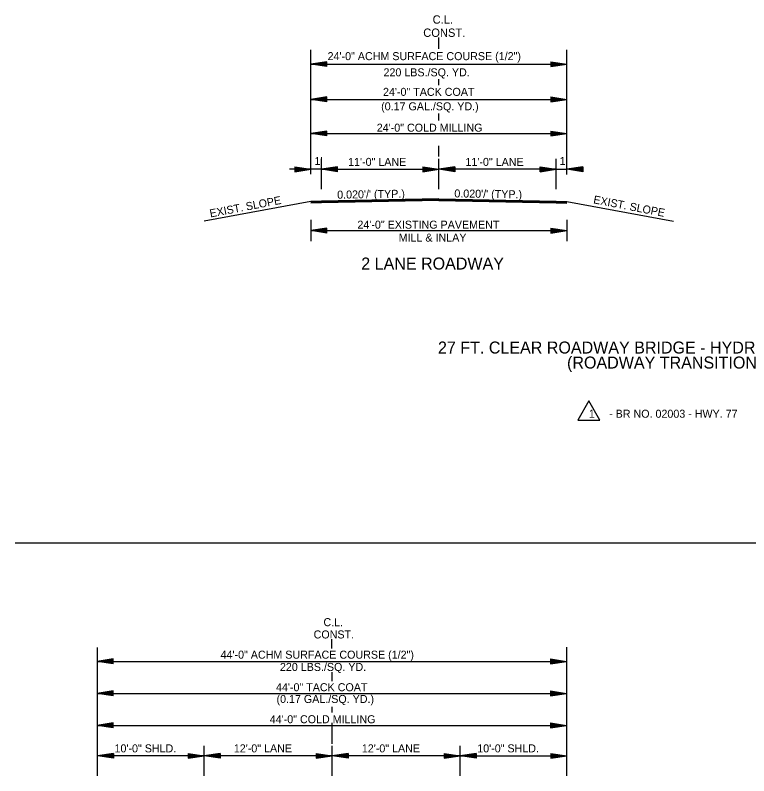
# Model space of a CAD drawing. Extents: x 549600 to 1930787, y -1955432 to 596640.
# Drawn here: x 551005 to 551693, y -1945136 to -1944424 of the extents above; entities that cross this region are included whole.
import ezdxf

# ---------------------------------------------------------------- set-up
doc = ezdxf.new("R2010")
doc.units = 0
doc.layers.add('R_Border', color=7, linetype='Continuous')
doc.layers.add('S_AREA_CALC', color=7, linetype='Continuous')

# ---------------------------------------------------------------- blocks, each defined once
blk = doc.blocks.new('ARROW')
at = {"layer": 'S_AREA_CALC'}
for p, q in [((-2, 0.3), (0, 0)), ((-2, 0.3), (-2, -0.3)), ((-2, 0.25), (-0.334, 0)), ((-2, 0.199), (-0.678, 0)), ((-2, 0.149), (-1.011, 0)), ((-2, 0.097), (-1.35, 0)), ((-2, 0.047), (-1.684, 0)), ((-2, -0.3), (0, 0)), ((-2, -0.098), (-1.35, 0)), ((-2, -0.199), (-0.678, 0)), ((-2, -0.25), (-0.334, 0)), ((-2, -0.149), (-1.011, 0)), ((-2, -0.047), (-1.684, 0))]:
    blk.add_line(p, q, dxfattribs=at)

msp = doc.modelspace()

# ---------------------------------------------------------------- linework, layer by layer
at = {"layer": 'R_Border'}
for p, q in [((551292.02, -1944597.88), (551282.02, -1944598.28)), ((551292.02, -1944598.18), (551282.02, -1944598.58)), ((551292.02, -1944598.48), (551282.02, -1944598.88)), ((551292.02, -1944598.78), (551282.02, -1944599.18)), ((551512.02, -1944597.88), (551522.02, -1944598.28)), ((551512.02, -1944598.18), (551522.02, -1944598.58)), ((551512.02, -1944598.48), (551522.02, -1944598.88)), ((551512.02, -1944598.78), (551522.02, -1944599.18)), ((551292.02, -1944599.08), (551282.02, -1944599.48)), ((551292.02, -1944599.38), (551282.02, -1944599.78)), ((551292.02, -1944599.55), (551282.02, -1944599.95)), ((551512.02, -1944599.08), (551522.02, -1944599.48)), ((551512.02, -1944599.38), (551522.02, -1944599.78)), ((551512.02, -1944599.55), (551522.02, -1944599.95)), ((551532.29, -1944803.08), (551552.96, -1944803.08)), ((551004.91, -1944917.94), (552066.18, -1944917.94)), ((551301.38, -1945008.4), (551301.38, -1945016.96)), ((551081.71, -1945029.1), (551521.71, -1945029.1)), ((551301.6, -1945039.33), (551301.6, -1945047.55)), ((551081.71, -1945059.1), (551521.71, -1945059.1)), ((551301.67, -1945071.61), (551301.67, -1945077.11)), ((551081.71, -1945089.1), (551521.71, -1945089.1))]:
    msp.add_line(p, q, dxfattribs=at)
msp.add_lwpolyline([(551552.96, -1944803.08), (551542.63, -1944785.18), (551532.29, -1944803.08)], dxfattribs=at)
at = {"layer": 'S_AREA_CALC'}
for p, q in [((551402.02, -1944455.12), (551402.02, -1944444.74)), ((551282.02, -1944572.61), (551282.02, -1944456.23)), ((551522.02, -1944573.09), (551522.02, -1944456.23)), ((551297.02, -1944467.35), (551282.02, -1944469.6)), ((551282.02, -1944469.6), (551522.02, -1944469.6)), ((551297.02, -1944471.85), (551282.02, -1944469.6)), ((551297.02, -1944467.73), (551284.52, -1944469.6)), ((551297.02, -1944471.48), (551284.52, -1944469.6)), ((551297.02, -1944468.11), (551287.1, -1944469.6)), ((551297.02, -1944471.09), (551287.1, -1944469.6)), ((551297.02, -1944468.48), (551289.6, -1944469.6)), ((551297.02, -1944470.72), (551289.6, -1944469.6)), ((551297.02, -1944468.87), (551292.14, -1944469.6)), ((551297.02, -1944470.33), (551292.14, -1944469.6)), ((551297.02, -1944469.25), (551294.65, -1944469.6)), ((551297.02, -1944469.95), (551294.65, -1944469.6)), ((551297.02, -1944471.85), (551297.02, -1944467.35)), ((551507.02, -1944467.35), (551522.02, -1944469.6)), ((551507.02, -1944467.35), (551507.02, -1944471.85)), ((551507.02, -1944467.73), (551519.51, -1944469.6)), ((551507.02, -1944468.11), (551516.93, -1944469.6)), ((551507.02, -1944468.48), (551514.44, -1944469.6)), ((551507.02, -1944468.87), (551511.89, -1944469.6)), ((551507.02, -1944469.25), (551509.39, -1944469.6)), ((551507.02, -1944471.85), (551522.02, -1944469.6)), ((551507.02, -1944470.34), (551511.89, -1944469.6)), ((551507.02, -1944471.09), (551516.93, -1944469.6)), ((551507.02, -1944471.48), (551519.51, -1944469.6)), ((551507.02, -1944470.72), (551514.44, -1944469.6)), ((551507.02, -1944469.95), (551509.39, -1944469.6)), ((551402.02, -1944489.34), (551402.02, -1944483.81)), ((551297.02, -1944500.32), (551282.02, -1944502.57)), ((551282.02, -1944502.57), (551522.02, -1944502.57)), ((551297.02, -1944504.82), (551282.02, -1944502.57)), ((551297.02, -1944500.69), (551284.52, -1944502.57)), ((551297.02, -1944504.44), (551284.52, -1944502.57)), ((551297.02, -1944501.07), (551287.1, -1944502.57)), ((551297.02, -1944504.06), (551287.1, -1944502.57)), ((551297.02, -1944501.45), (551289.6, -1944502.57)), ((551297.02, -1944503.68), (551289.6, -1944502.57)), ((551297.02, -1944501.83), (551292.14, -1944502.57)), ((551297.02, -1944503.29), (551292.14, -1944502.57)), ((551297.02, -1944502.21), (551294.65, -1944502.57)), ((551297.02, -1944502.92), (551294.65, -1944502.57)), ((551297.02, -1944504.82), (551297.02, -1944500.32)), ((551507.02, -1944500.32), (551522.02, -1944502.57)), ((551507.02, -1944500.32), (551507.02, -1944504.82)), ((551507.02, -1944500.69), (551519.51, -1944502.57)), ((551507.02, -1944501.07), (551516.93, -1944502.57)), ((551507.02, -1944501.45), (551514.44, -1944502.57)), ((551507.02, -1944501.84), (551511.89, -1944502.57)), ((551507.02, -1944502.21), (551509.39, -1944502.57)), ((551507.02, -1944504.82), (551522.02, -1944502.57)), ((551507.02, -1944503.3), (551511.89, -1944502.57)), ((551507.02, -1944504.06), (551516.93, -1944502.57)), ((551507.02, -1944504.44), (551519.51, -1944502.57)), ((551507.02, -1944503.68), (551514.44, -1944502.57)), ((551507.02, -1944502.92), (551509.39, -1944502.57)), ((551402.02, -1944522.31), (551402.02, -1944515.89)), ((551297.02, -1944532.29), (551282.02, -1944534.54)), ((551282.02, -1944534.54), (551522.02, -1944534.54)), ((551297.02, -1944536.79), (551282.02, -1944534.54)), ((551297.02, -1944532.67), (551284.52, -1944534.54)), ((551297.02, -1944536.42), (551284.52, -1944534.54)), ((551297.02, -1944533.05), (551287.1, -1944534.54)), ((551297.02, -1944536.03), (551287.1, -1944534.54)), ((551297.02, -1944533.42), (551289.6, -1944534.54)), ((551297.02, -1944535.66), (551289.6, -1944534.54)), ((551297.02, -1944533.81), (551292.14, -1944534.54)), ((551297.02, -1944535.27), (551292.14, -1944534.54)), ((551297.02, -1944534.19), (551294.65, -1944534.54)), ((551297.02, -1944534.89), (551294.65, -1944534.54)), ((551297.02, -1944536.79), (551297.02, -1944532.29)), ((551507.02, -1944532.29), (551522.02, -1944534.54)), ((551507.02, -1944532.29), (551507.02, -1944536.79)), ((551507.02, -1944532.67), (551519.51, -1944534.54)), ((551507.02, -1944533.05), (551516.93, -1944534.54)), ((551507.02, -1944533.42), (551514.44, -1944534.54)), ((551507.02, -1944533.81), (551511.89, -1944534.54)), ((551507.02, -1944534.19), (551509.39, -1944534.54)), ((551507.02, -1944536.79), (551522.02, -1944534.54)), ((551507.02, -1944535.28), (551511.89, -1944534.54)), ((551507.02, -1944536.03), (551516.93, -1944534.54)), ((551507.02, -1944536.42), (551519.51, -1944534.54)), ((551507.02, -1944535.66), (551514.44, -1944534.54)), ((551507.02, -1944534.89), (551509.39, -1944534.54)), ((551402.02, -1944556.06), (551402.02, -1944546.19)), ((551292.02, -1944586.74), (551292.02, -1944558.19)), ((551402.02, -1944586.74), (551402.02, -1944558.19)), ((551512.02, -1944586.74), (551512.02, -1944558.19)), ((551292.02, -1944568.08), (551262.02, -1944568.08)), ((551267.02, -1944565.83), (551282.02, -1944568.08)), ((551267.02, -1944565.83), (551267.02, -1944570.33)), ((551267.02, -1944566.2), (551279.51, -1944568.08)), ((551267.02, -1944566.59), (551276.93, -1944568.08)), ((551267.02, -1944566.96), (551274.44, -1944568.08)), ((551267.02, -1944567.35), (551271.89, -1944568.08)), ((551267.02, -1944567.73), (551269.39, -1944568.08)), ((551267.02, -1944570.33), (551282.02, -1944568.08)), ((551267.02, -1944568.81), (551271.89, -1944568.08)), ((551267.02, -1944569.57), (551276.93, -1944568.08)), ((551267.02, -1944569.95), (551279.51, -1944568.08)), ((551267.02, -1944569.2), (551274.44, -1944568.08)), ((551267.02, -1944568.43), (551269.39, -1944568.08)), ((551307.02, -1944565.83), (551292.02, -1944568.08)), ((551307.02, -1944570.33), (551292.02, -1944568.08)), ((551292.02, -1944568.08), (551402.02, -1944568.08)), ((551307.02, -1944566.2), (551294.52, -1944568.08)), ((551307.02, -1944569.95), (551294.52, -1944568.08)), ((551307.02, -1944566.59), (551297.1, -1944568.08)), ((551307.02, -1944569.57), (551297.1, -1944568.08)), ((551307.02, -1944566.96), (551299.6, -1944568.08)), ((551307.02, -1944569.2), (551299.6, -1944568.08)), ((551307.02, -1944567.34), (551302.14, -1944568.08)), ((551307.02, -1944568.81), (551302.14, -1944568.08)), ((551307.02, -1944567.73), (551304.65, -1944568.08)), ((551307.02, -1944568.43), (551304.65, -1944568.08)), ((551307.02, -1944570.33), (551307.02, -1944565.83)), ((551387.02, -1944565.83), (551402.02, -1944568.08)), ((551387.02, -1944565.83), (551387.02, -1944570.33)), ((551387.02, -1944566.2), (551399.51, -1944568.08)), ((551387.02, -1944566.59), (551396.93, -1944568.08)), ((551387.02, -1944566.96), (551394.44, -1944568.08)), ((551387.02, -1944567.35), (551391.89, -1944568.08)), ((551387.02, -1944567.73), (551389.39, -1944568.08)), ((551387.02, -1944570.33), (551402.02, -1944568.08)), ((551387.02, -1944568.81), (551391.89, -1944568.08)), ((551387.02, -1944569.57), (551396.93, -1944568.08)), ((551387.02, -1944569.95), (551399.51, -1944568.08)), ((551387.02, -1944569.2), (551394.44, -1944568.08)), ((551387.02, -1944568.43), (551389.39, -1944568.08)), ((551417.02, -1944565.83), (551402.02, -1944568.08)), ((551512.02, -1944568.08), (551402.02, -1944568.08)), ((551417.02, -1944570.33), (551402.02, -1944568.08)), ((551417.02, -1944566.2), (551404.52, -1944568.08)), ((551417.02, -1944569.95), (551404.52, -1944568.08)), ((551417.02, -1944566.59), (551407.1, -1944568.08)), ((551417.02, -1944569.57), (551407.1, -1944568.08)), ((551417.02, -1944566.96), (551409.6, -1944568.08)), ((551417.02, -1944569.2), (551409.6, -1944568.08)), ((551417.02, -1944567.35), (551412.14, -1944568.08)), ((551417.02, -1944568.81), (551412.14, -1944568.08)), ((551417.02, -1944567.73), (551414.65, -1944568.08)), ((551417.02, -1944568.43), (551414.65, -1944568.08)), ((551417.02, -1944565.83), (551417.02, -1944570.33)), ((551497.02, -1944565.83), (551512.02, -1944568.08)), ((551497.02, -1944570.33), (551497.02, -1944565.83)), ((551497.02, -1944566.2), (551509.51, -1944568.08)), ((551497.02, -1944566.59), (551506.93, -1944568.08)), ((551497.02, -1944566.96), (551504.44, -1944568.08)), ((551497.02, -1944567.34), (551501.89, -1944568.08)), ((551497.02, -1944567.73), (551499.39, -1944568.08)), ((551497.02, -1944570.33), (551512.02, -1944568.08)), ((551497.02, -1944568.81), (551501.89, -1944568.08)), ((551497.02, -1944569.57), (551506.93, -1944568.08)), ((551497.02, -1944569.95), (551509.51, -1944568.08)), ((551497.02, -1944569.2), (551504.44, -1944568.08)), ((551497.02, -1944568.43), (551499.39, -1944568.08)), ((551512.02, -1944568.08), (551522.02, -1944568.08)), ((551537.02, -1944565.83), (551522.02, -1944568.08)), ((551537.02, -1944570.33), (551522.02, -1944568.08)), ((551537.02, -1944566.2), (551524.52, -1944568.08)), ((551537.02, -1944569.95), (551524.52, -1944568.08)), ((551537.02, -1944566.59), (551527.1, -1944568.08)), ((551537.02, -1944569.57), (551527.1, -1944568.08)), ((551537.02, -1944566.96), (551529.6, -1944568.08)), ((551537.02, -1944569.2), (551529.6, -1944568.08)), ((551537.02, -1944567.35), (551532.14, -1944568.08)), ((551537.02, -1944568.81), (551532.14, -1944568.08)), ((551537.02, -1944567.73), (551534.65, -1944568.08)), ((551537.02, -1944568.43), (551534.65, -1944568.08)), ((551537.02, -1944565.83), (551537.02, -1944570.33)), ((551282.02, -1944598.28), (551181.95, -1944616.66)), ((551402.02, -1944595.68), (551292.02, -1944597.88)), ((551402.05, -1944595.98), (551292.02, -1944598.18)), ((551402.04, -1944596.28), (551292.02, -1944598.48)), ((551402.04, -1944596.58), (551292.02, -1944598.78)), ((551402.04, -1944596.88), (551292.02, -1944599.08)), ((551402.05, -1944597.18), (551292.02, -1944599.38)), ((551402.05, -1944597.35), (551292.02, -1944599.55)), ((551401.98, -1944597.35), (551512.02, -1944599.55)), ((551401.99, -1944596.88), (551512.02, -1944599.08)), ((551401.99, -1944597.18), (551512.02, -1944599.38)), ((551402, -1944596.58), (551512.02, -1944598.78)), ((551402.01, -1944595.98), (551512.02, -1944598.18)), ((551402.01, -1944596.28), (551512.02, -1944598.48)), ((551402.02, -1944595.68), (551512.02, -1944597.88)), ((551522.02, -1944598.28), (551622.09, -1944616.66)), ((551282.02, -1944615.54), (551282.02, -1944635.54)), ((551522.02, -1944615.54), (551522.02, -1944635.54)), ((551297.02, -1944623.29), (551282.02, -1944625.54)), ((551282.02, -1944625.54), (551522.02, -1944625.54)), ((551297.02, -1944627.79), (551282.02, -1944625.54)), ((551297.02, -1944623.67), (551284.52, -1944625.54)), ((551297.02, -1944627.42), (551284.52, -1944625.54)), ((551297.02, -1944624.05), (551287.1, -1944625.54)), ((551297.02, -1944627.04), (551287.1, -1944625.54)), ((551297.02, -1944624.43), (551289.6, -1944625.54)), ((551297.02, -1944626.66), (551289.6, -1944625.54)), ((551297.02, -1944624.81), (551292.14, -1944625.54)), ((551297.02, -1944626.27), (551292.14, -1944625.54)), ((551297.02, -1944625.19), (551294.65, -1944625.54)), ((551297.02, -1944625.9), (551294.65, -1944625.54)), ((551297.02, -1944627.79), (551297.02, -1944623.29)), ((551507.02, -1944623.29), (551522.02, -1944625.54)), ((551507.02, -1944623.29), (551507.02, -1944627.79)), ((551507.02, -1944623.67), (551519.51, -1944625.54)), ((551507.02, -1944624.05), (551516.93, -1944625.54)), ((551507.02, -1944624.43), (551514.44, -1944625.54)), ((551507.02, -1944624.82), (551511.89, -1944625.54)), ((551507.02, -1944625.19), (551509.39, -1944625.54)), ((551507.02, -1944627.79), (551522.02, -1944625.54)), ((551507.02, -1944626.28), (551511.89, -1944625.54)), ((551507.02, -1944627.04), (551516.93, -1944625.54)), ((551507.02, -1944627.42), (551519.51, -1944625.54)), ((551507.02, -1944626.66), (551514.44, -1944625.54)), ((551507.02, -1944625.9), (551509.39, -1944625.54)), ((551082.02, -1945136.32), (551082.02, -1945016.26)), ((551522.02, -1945136.32), (551522.02, -1945015.87)), ((551302.02, -1945098.26), (551302.02, -1945086.81)), ((551302.02, -1945106.25), (551302.02, -1945098.26)), ((551182.02, -1945136.32), (551182.02, -1945108.37)), ((551302.02, -1945136.32), (551302.02, -1945108.37)), ((551422.02, -1945136.32), (551422.02, -1945108.37)), ((551097.02, -1945115.31), (551082.02, -1945117.56)), ((551182.02, -1945117.56), (551082.02, -1945117.56)), ((551097.02, -1945119.81), (551082.02, -1945117.56)), ((551097.02, -1945115.69), (551084.52, -1945117.56)), ((551097.02, -1945119.44), (551084.52, -1945117.56)), ((551097.02, -1945116.07), (551087.1, -1945117.56)), ((551097.02, -1945119.05), (551087.1, -1945117.56)), ((551097.02, -1945116.44), (551089.6, -1945117.56)), ((551097.02, -1945118.68), (551089.6, -1945117.56)), ((551097.02, -1945116.83), (551092.14, -1945117.56)), ((551097.02, -1945118.3), (551092.14, -1945117.56)), ((551097.02, -1945117.21), (551094.65, -1945117.56)), ((551097.02, -1945117.91), (551094.65, -1945117.56)), ((551097.02, -1945115.31), (551097.02, -1945119.81)), ((551167.02, -1945115.31), (551182.02, -1945117.56)), ((551167.02, -1945115.31), (551167.02, -1945119.81)), ((551167.02, -1945115.69), (551179.51, -1945117.56)), ((551167.02, -1945116.07), (551176.93, -1945117.56)), ((551167.02, -1945116.44), (551174.44, -1945117.56)), ((551167.02, -1945116.83), (551171.89, -1945117.56)), ((551167.02, -1945117.21), (551169.39, -1945117.56)), ((551167.02, -1945119.81), (551182.02, -1945117.56)), ((551167.02, -1945118.3), (551171.89, -1945117.56)), ((551167.02, -1945119.05), (551176.93, -1945117.56)), ((551167.02, -1945119.44), (551179.51, -1945117.56)), ((551167.02, -1945118.68), (551174.44, -1945117.56)), ((551167.02, -1945117.91), (551169.39, -1945117.56)), ((551197.02, -1945115.31), (551182.02, -1945117.56)), ((551302.02, -1945117.56), (551182.02, -1945117.56)), ((551197.02, -1945119.81), (551182.02, -1945117.56)), ((551197.02, -1945115.69), (551184.52, -1945117.56)), ((551197.02, -1945119.44), (551184.52, -1945117.56)), ((551197.02, -1945116.07), (551187.1, -1945117.56)), ((551197.02, -1945119.05), (551187.1, -1945117.56)), ((551197.02, -1945116.44), (551189.6, -1945117.56)), ((551197.02, -1945118.68), (551189.6, -1945117.56)), ((551197.02, -1945116.83), (551192.14, -1945117.56)), ((551197.02, -1945118.3), (551192.14, -1945117.56)), ((551197.02, -1945117.21), (551194.65, -1945117.56)), ((551197.02, -1945117.91), (551194.65, -1945117.56)), ((551197.02, -1945115.31), (551197.02, -1945119.81)), ((551287.02, -1945115.31), (551302.02, -1945117.56)), ((551287.02, -1945115.31), (551287.02, -1945119.81)), ((551287.02, -1945115.69), (551299.51, -1945117.56)), ((551287.02, -1945116.07), (551296.93, -1945117.56)), ((551287.02, -1945116.44), (551294.44, -1945117.56)), ((551287.02, -1945116.83), (551291.89, -1945117.56)), ((551287.02, -1945117.21), (551289.39, -1945117.56)), ((551287.02, -1945119.81), (551302.02, -1945117.56)), ((551287.02, -1945118.3), (551291.89, -1945117.56)), ((551287.02, -1945119.05), (551296.93, -1945117.56)), ((551287.02, -1945119.44), (551299.51, -1945117.56)), ((551287.02, -1945118.68), (551294.44, -1945117.56)), ((551287.02, -1945117.91), (551289.39, -1945117.56)), ((551317.02, -1945115.31), (551302.02, -1945117.56)), ((551422.02, -1945117.56), (551302.02, -1945117.56)), ((551317.02, -1945119.81), (551302.02, -1945117.56)), ((551317.02, -1945115.69), (551304.52, -1945117.56)), ((551317.02, -1945119.44), (551304.52, -1945117.56)), ((551317.02, -1945116.07), (551307.1, -1945117.56)), ((551317.02, -1945119.05), (551307.1, -1945117.56)), ((551317.02, -1945116.44), (551309.6, -1945117.56)), ((551317.02, -1945118.68), (551309.6, -1945117.56)), ((551317.02, -1945116.83), (551312.14, -1945117.56)), ((551317.02, -1945118.3), (551312.14, -1945117.56)), ((551317.02, -1945117.21), (551314.65, -1945117.56)), ((551317.02, -1945117.91), (551314.65, -1945117.56)), ((551317.02, -1945115.31), (551317.02, -1945119.81)), ((551407.02, -1945115.31), (551422.02, -1945117.56)), ((551407.02, -1945115.31), (551407.02, -1945119.81)), ((551407.02, -1945115.69), (551419.51, -1945117.56)), ((551407.02, -1945116.07), (551416.93, -1945117.56)), ((551407.02, -1945116.44), (551414.44, -1945117.56)), ((551407.02, -1945116.83), (551411.89, -1945117.56)), ((551407.02, -1945117.21), (551409.39, -1945117.56)), ((551407.02, -1945119.81), (551422.02, -1945117.56)), ((551407.02, -1945118.3), (551411.89, -1945117.56)), ((551407.02, -1945119.05), (551416.93, -1945117.56)), ((551407.02, -1945119.44), (551419.51, -1945117.56)), ((551407.02, -1945118.68), (551414.44, -1945117.56)), ((551407.02, -1945117.91), (551409.39, -1945117.56)), ((551437.02, -1945115.31), (551422.02, -1945117.56)), ((551422.02, -1945117.56), (551522.02, -1945117.56)), ((551437.02, -1945119.81), (551422.02, -1945117.56)), ((551437.02, -1945115.69), (551424.52, -1945117.56)), ((551437.02, -1945119.44), (551424.52, -1945117.56)), ((551437.02, -1945116.07), (551427.1, -1945117.56)), ((551437.02, -1945119.05), (551427.1, -1945117.56)), ((551437.02, -1945116.44), (551429.6, -1945117.56)), ((551437.02, -1945118.68), (551429.6, -1945117.56)), ((551437.02, -1945116.83), (551432.14, -1945117.56)), ((551437.02, -1945118.3), (551432.14, -1945117.56)), ((551437.02, -1945117.21), (551434.65, -1945117.56)), ((551437.02, -1945117.91), (551434.65, -1945117.56)), ((551437.02, -1945115.31), (551437.02, -1945119.81)), ((551507.02, -1945115.31), (551522.02, -1945117.56)), ((551507.02, -1945115.31), (551507.02, -1945119.81)), ((551507.02, -1945115.69), (551519.51, -1945117.56)), ((551507.02, -1945116.07), (551516.93, -1945117.56)), ((551507.02, -1945116.44), (551514.44, -1945117.56)), ((551507.02, -1945116.83), (551511.89, -1945117.56)), ((551507.02, -1945117.21), (551509.39, -1945117.56)), ((551507.02, -1945119.81), (551522.02, -1945117.56)), ((551507.02, -1945118.3), (551511.89, -1945117.56)), ((551507.02, -1945119.05), (551516.93, -1945117.56)), ((551507.02, -1945119.44), (551519.51, -1945117.56)), ((551507.02, -1945118.68), (551514.44, -1945117.56)), ((551507.02, -1945117.91), (551509.39, -1945117.56))]:
    msp.add_line(p, q, dxfattribs=at)

# ---------------------------------------------------------------- block references
at = {"layer": 'R_Border', "xscale": 7.5, "yscale": 7.5, "rotation": 180}
for p in [(551081.71, -1945029.1), (551081.71, -1945059.1), (551081.71, -1945089.1)]:
    msp.add_blockref('ARROW', p, dxfattribs=at)
at = {"layer": 'R_Border', "xscale": 7.5, "yscale": 7.5}
for p in [(551521.71, -1945029.1), (551521.71, -1945059.1), (551521.71, -1945089.1)]:
    msp.add_blockref('ARROW', p, dxfattribs=at)

# ---------------------------------------------------------------- texts
at = {"layer": 'R_Border'}
for s, height, p in [('27 FT. CLEAR ROADWAY BRIDGE - HYDRODEMOLITION', 11.25, (551401.23, -1944740.7)), ('(ROADWAY TRANSITIONS)', 11.25, (551522.18, -1944754.78)), ('1', 7.5, (551542.63, -1944800.86)), ('- BR NO. 02003 - HWY. 77', 7.5, (551561.63, -1944800.86)), ('C.L.', 7.5, (551293.86, -1944996.15)), ('CONST.', 7.5, (551284.64, -1945007.65)), ('44\'-0" ACHM SURFACE COURSE (1/2")', 7.5, (551197.42, -1945026.6)), ('220 LBS./SQ. YD.', 7.5, (551253.05, -1945038.1)), ('44\'-0" TACK COAT', 7.5, (551249.36, -1945057.1)), ('(0.17 GAL./SQ. YD.)', 7.5, (551249.86, -1945068.1)), ('44\'-0" COLD MILLING', 7.5, (551243.51, -1945087.1))]:
    msp.add_text(s, height=height, dxfattribs=at).set_placement(p)
at = {"layer": 'S_AREA_CALC'}
for s, height, p in [('C.L.', 7.8, (551396.17, -1944431.65)), ('CONST.', 7.8, (551387.39, -1944444.02)), ('24\'-0" ACHM SURFACE COURSE (1/2")', 7.5, (551297.73, -1944465.83)), ('220 LBS./SQ. YD. ', 7.5, (551350.14, -1944481.01)), ('24\'-0" TACK COAT', 7.5, (551349.67, -1944499.3)), ('(0.17 GAL./SQ. YD.)', 7.5, (551347.93, -1944512.85)), ('24\'-0" COLD MILLING ', 7.5, (551343.82, -1944532.87)), ("1'", 7.5, (551285.43, -1944564.09)), ('11\'-0" LANE', 7.5, (551316.96, -1944564.91)), ('11\'-0" LANE', 7.5, (551426.96, -1944564.91)), ("1'", 7.5, (551515.19, -1944564.09)), ('24\'-0" EXISTING PAVEMENT', 7.5, (551325.69, -1944623.71)), ('MILL & INLAY', 7.5, (551364.34, -1944635.8)), ('2 LANE ROADWAY', 11.25, (551329.29, -1944662.01)), ('10\'-0" SHLD.', 7.5, (551098, -1945114.39)), ('12\'-0" LANE', 7.5, (551209.83, -1945114.39)), ('12\'-0" LANE', 7.5, (551329.83, -1945114.39)), ('10\'-0" SHLD.', 7.5, (551438, -1945114.39))]:
    msp.add_text(s, height=height, dxfattribs=at).set_placement(p)
for s, rotation, p in [("0.020'/' (TYP.)", 0.87191, (551306.76, -1944595.64)), ("0.020'/' (TYP.)", 359.12809, (551416.5, -1944594.41)), ('EXIST. SLOPE', 10.88286, (551187.93, -1944613.28)), ('EXIST. SLOPE', 349.11714, (551546.4, -1944599.88))]:
    msp.add_text(s, height=7.5, rotation=rotation, dxfattribs=at).set_placement(p)

doc.saveas('drawing.dxf')
